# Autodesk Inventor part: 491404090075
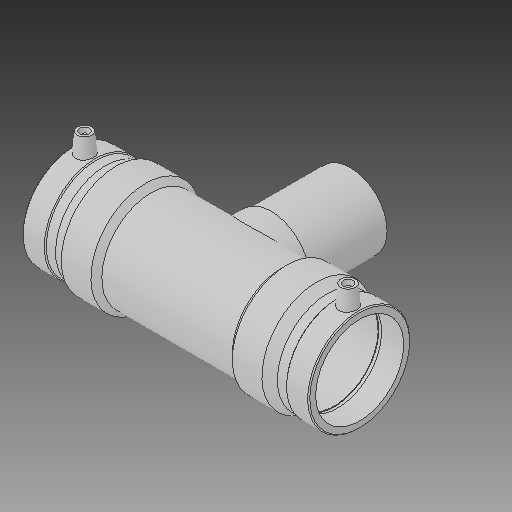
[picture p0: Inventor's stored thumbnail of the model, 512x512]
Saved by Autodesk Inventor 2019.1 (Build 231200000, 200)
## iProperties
Created: 2017-06
Part Number: 491404090075
Material: Generic
Description: PLASSON REDUCING TEE 90x75x90
Document SubType Name: Modeling
Designer: KIM
Mass: 5000.41 g
Surface Area: 5471.45 cm^2
Volume: 5000.41 cm^3
Density: 1 g/cm^3
Appearance: Default
Author: KIM
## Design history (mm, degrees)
derived "491404.ipt"
feature "Solid1::491404.ipt"
tag "TaggingFeature1"
body "Solid1"
other parameters: "L_" = 293, "L_1" = 71, "D_" = 112, "A_" = 71, "d_2" = 12, "H_" = 137, "d_1" = 75, "d0" = 293, "d2" = 112, "d3" = 71, "d4" = 58.6, "d5" = 100.8, "d6" = 85.5, "d8" = 168 deg, "d10" = 28.4, "d11" = 9.46667, "d13" = 293, "d14" = 17.6296, "d17" = 81, "d19" = 3.52592, "d20" = 168 deg, "d22" = 104.16, "d23" = 112, "d25" = 135 deg, "d26" = 205.1, "d29" = 71, "d30" = 15, "d31" = 117.2, "d34" = 5 deg, "d35" = 15, "d39" = 5 deg, "d41" = 4, "d42" = 14, "d43" = 0, "d45" = 4, "d46" = 6, "d47" = 0, "d48" = -137, "d49" = 75, "d51" = 0, "d54" = 0, "d55" = 100.8, "d56" = 112, "d57" = 102.55, "d58" = 135 deg, "d59" = 71, "d60" = 71, "d61" = 135 deg, "d62" = 137, "d72" = 133.315, "d73" = 66.6575, "d74" = -137, "d75" = 78.75, "d77" = 0, "d80" = 0, "d81" = 75, "d82" = 81, "d83" = 0, "d84" = 3, "d85" = 0, "d86" = 23.66667, "d87" = 102.0768, "d88" = 9.46667, "d89" = 3, "d90" = 0
